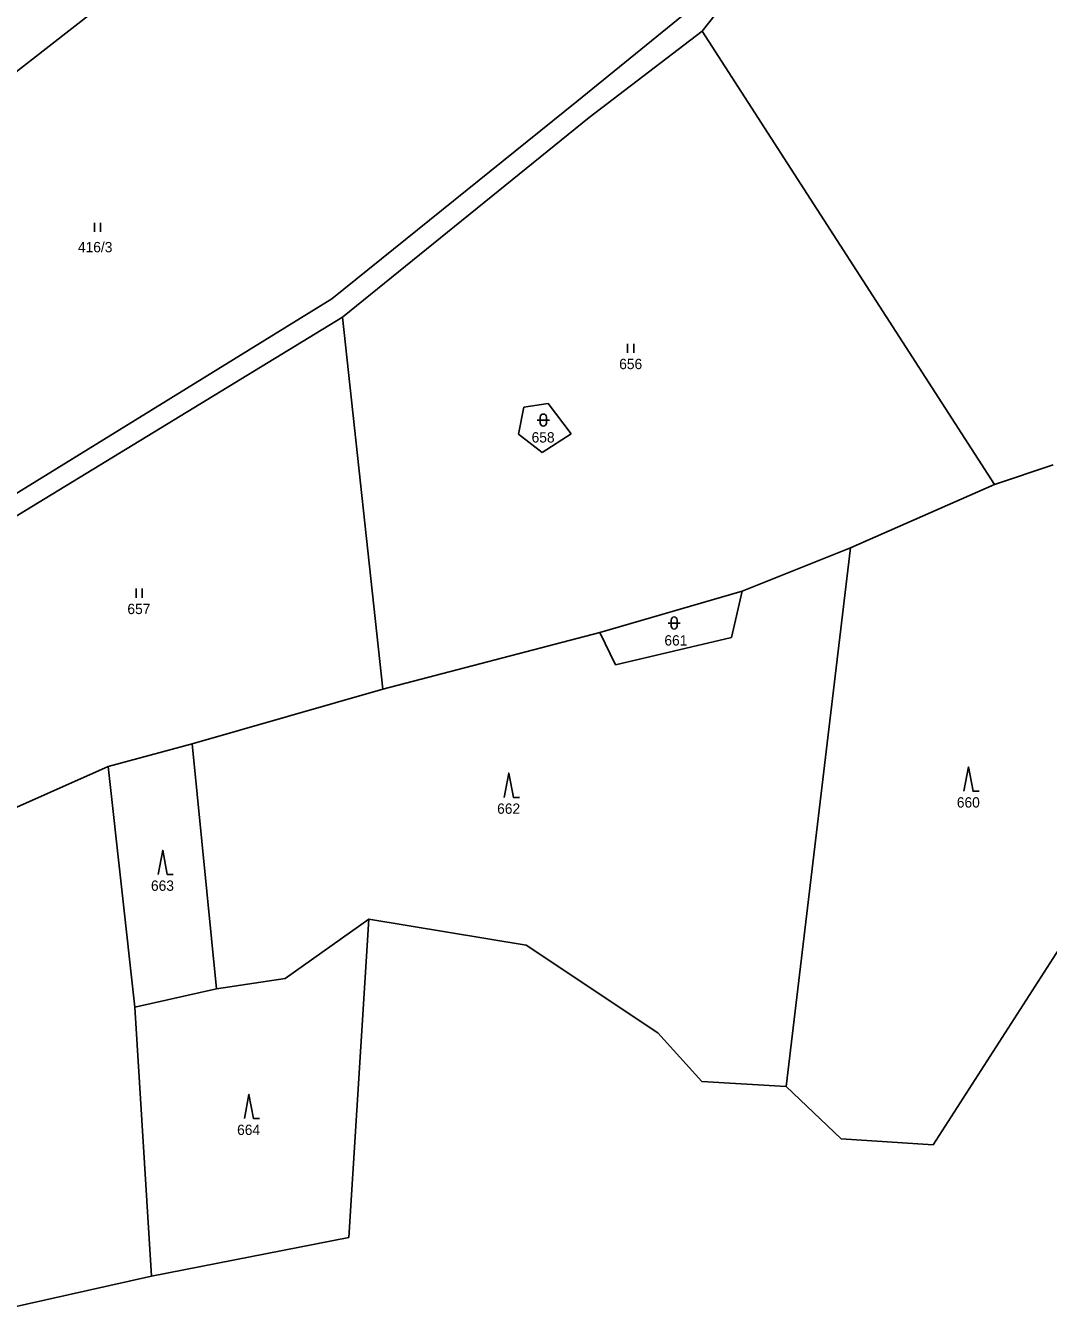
# Model space of a CAD drawing. Extents: x -670359 to -660124, y -978807 to -970072.
# Drawn here: x -668454.3 to -668285.6, y -977793.3 to -977581.7 of the extents above; entities that cross this region are included whole.
import ezdxf

# ---------------------------------------------------------------- set-up
doc = ezdxf.new("R2010")
doc.units = 0
for name, color, linetype in [('Hranice kat_území', 7, 'Continuous'), ('Hranice parcel', 7, 'Continuous'), ('Parcelní čísla', 7, 'Continuous'), ('Značky kultur', 7, 'Continuous')]:
    doc.layers.add(name, color=color, linetype=linetype)

msp = doc.modelspace()

# ---------------------------------------------------------------- linework, layer by layer
at = {"layer": 'Hranice kat_území'}
for points in [[(-668400.99, -977781.5), (-668397.7, -977729.04)], [(-668397.7, -977729.04), (-668371.74, -977733.31)], [(-668371.74, -977733.31), (-668349.99, -977747.76)], [(-668304.59, -977766.25), (-668283.32, -977733.14)], [(-668349.99, -977747.76), (-668342.74, -977755.78)], [(-668342.74, -977755.78), (-668328.84, -977756.59)], [(-668328.84, -977756.59), (-668319.77, -977765.23)], [(-668319.77, -977765.23), (-668304.59, -977766.25)], [(-668433.57, -977787.88), (-668400.99, -977781.5)], [(-668457.87, -977793.35), (-668433.57, -977787.88)]]:
    msp.add_lwpolyline(points, dxfattribs=at)
at = {"layer": 'Hranice parcel'}
for points in [[(-668508.63, -977630.34), (-668419.28, -977560.69)], [(-668342.72, -977582.59), (-668333.08, -977570.37)], [(-668344.92, -977579.16), (-668363.39, -977594.19)], [(-668361.32, -977596.83), (-668342.72, -977582.59)], [(-668342.72, -977582.59), (-668294.5, -977657.36)], [(-668363.39, -977594.19), (-668403.78, -977626.71)], [(-668402.04, -977629.73), (-668361.32, -977596.83)], [(-668403.78, -977626.71), (-668460.27, -977661.53)], [(-668458.93, -977664.38), (-668402.04, -977629.73)], [(-668402.04, -977629.73), (-668395.4, -977691.1)], [(-668373, -977649.05), (-668372.1, -977644.6)], [(-668372.1, -977644.6), (-668368.1, -977644)], [(-668368.1, -977644), (-668364.3, -977649)], [(-668369.1, -977652.05), (-668373, -977649.05)], [(-668364.3, -977649), (-668369.1, -977652.05)], [(-668294.5, -977657.36), (-668284.78, -977654.1)], [(-668318.25, -977667.81), (-668294.5, -977657.36)], [(-668336.13, -977674.94), (-668318.25, -977667.81)], [(-668318.25, -977667.81), (-668328.84, -977756.59)], [(-668359.59, -977681.72), (-668336.13, -977674.94)], [(-668337.84, -977682.57), (-668336.13, -977674.94)], [(-668395.4, -977691.1), (-668359.59, -977681.72)], [(-668359.59, -977681.72), (-668356.98, -977687.09)], [(-668356.98, -977687.09), (-668337.84, -977682.57)], [(-668426.87, -977700.08), (-668395.4, -977691.1)], [(-668440.7, -977703.84), (-668426.87, -977700.08)], [(-668426.87, -977700.08), (-668422.85, -977740.48)], [(-668460.3, -977712.51), (-668440.7, -977703.84)], [(-668440.7, -977703.84), (-668436.33, -977743.53)], [(-668411.5, -977738.8), (-668397.7, -977729.04)], [(-668422.85, -977740.48), (-668411.5, -977738.8)], [(-668422.85, -977740.48), (-668436.33, -977743.53)], [(-668436.33, -977743.53), (-668433.57, -977787.88)]]:
    msp.add_lwpolyline(points, dxfattribs=at)
at = {"layer": 'Značky kultur'}
for p, q in [((-668442.96, -977614.17), (-668442.96, -977615.67)), ((-668441.96, -977615.67), (-668441.96, -977614.17)), ((-668355, -977634.12), (-668355, -977635.62)), ((-668354, -977635.62), (-668354, -977634.12)), ((-668369.91, -977646.72), (-668367.91, -977646.72)), ((-668369.41, -977646.22), (-668369.41, -977647.22)), ((-668368.41, -977646.22), (-668368.41, -977647.22)), ((-668436.1, -977674.51), (-668436.1, -977676.01)), ((-668435.1, -977676.01), (-668435.1, -977674.51)), ((-668348.32, -977680.19), (-668346.32, -977680.19)), ((-668347.82, -977679.69), (-668347.82, -977680.69)), ((-668346.82, -977679.69), (-668346.82, -977680.69))]:
    msp.add_line(p, q, dxfattribs=at)
for points in [[(-668299.51, -977707.91), (-668298.76, -977703.91), (-668298.01, -977707.91), (-668297.01, -977707.91)], [(-668375.35, -977708.94), (-668374.6, -977704.94), (-668373.85, -977708.94), (-668372.85, -977708.94)], [(-668432.46, -977721.64), (-668431.71, -977717.64), (-668430.96, -977721.64), (-668429.96, -977721.64)], [(-668418.22, -977761.9), (-668417.47, -977757.9), (-668416.72, -977761.9), (-668415.72, -977761.9)]]:
    msp.add_lwpolyline(points, dxfattribs=at)
for centre, start, end in [((-668368.91, -977646.22), 0, 180), ((-668368.91, -977647.22), 180, 0), ((-668347.32, -977679.69), 0, 180), ((-668347.32, -977680.69), 180, 0)]:
    msp.add_arc(centre, 0.5, start, end, dxfattribs=at)

# ---------------------------------------------------------------- texts
at = {"layer": 'Parcelní čísla'}
for s, p in [('416/3', (-668445.69, -977619.05)), ('656', (-668356.39, -977638.32)), ('658', (-668370.84, -977650.42)), ('657', (-668437.53, -977678.71)), ('661', (-668348.93, -977683.89)), ('662', (-668376.53, -977711.64)), ('660', (-668300.69, -977710.61)), ('663', (-668433.64, -977724.34)), ('664', (-668419.43, -977764.6))]:
    msp.add_text(s, height=1.7, dxfattribs=at).set_placement(p)

doc.saveas('drawing.dxf')
